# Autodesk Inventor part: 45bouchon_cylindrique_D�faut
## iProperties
Created: 2011-01
Part Number: 45bouchon_cylindrique_D�faut
Document SubType Name: Modeling
Designer: eric
Density: 1 g/cm^3
Mass: 3.69837 g
Surface Area: 38.7711 cm^2
Volume: 3.69837 cm^3
Author: eric
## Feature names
1. Base1
